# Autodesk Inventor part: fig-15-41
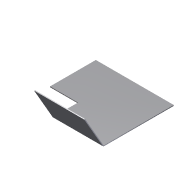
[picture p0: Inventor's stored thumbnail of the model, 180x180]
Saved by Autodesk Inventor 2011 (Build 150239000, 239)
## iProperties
Created: 2005-03
Part Number: fig-15-41
Document SubType Name: Sheet Metal
Designer: CADCIM
Manufacturer: Standard
Standards Organization: Custom
Density: 1 g/cm^3
Sheet Metal Rule: Default
Author: CADCIM
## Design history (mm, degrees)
node "Face1"
  sketch "Sketch1"
    geometry: L1 (31.393, 35.714)-(-19.875, 35.714); L2 (-19.875, 35.714)-(-19.875, 5.625); L3 (-19.875, 5.625)-(-1.5, 5.625); L4 (-1.5, 5.625)-(-1.5, -10.705); L5 (-1.5, -10.705)-(31.393, -10.705); L6 (31.393, -10.705)-(31.393, 35.714)
    constraints: 12 end point, 4 parallel, 1 horizontal, 1 perpendicular
sketch "Sketch3"
  geometry: L1 (18.375, -30.089)-(18.375, 0); L2 (18.375, -46.42)-(18.375, -30.089) reference; L3 (18.375, -30.089)-(0, -30.089) reference; L4 (0, 0)-(51.268, 0) reference
  constraints: 3 point on line, 2 end point, 1 vertical
node "Flange1"
body "Solid1"
face "Plate1" dims "Thickness" = 0.5
sketch "Sketch4"
  geometry: L1 (0, 25)-(-32.893, 25); L2 (-32.893, 25)-(-32.893, 0); 2 other entities
  constraints: 4 end point, 4 other
face "Plate2" dims "d1" = 0.5 (= BendReliefWidth), "d2" = 0.25 (= BendReliefDepth), "d3" = 1 (= MinimumRemnant), "d4" = 0.5 (= BendRadius), "d5" = 25, "d6" = 60 deg, "d7" = 0.5 (= BendRadius), "d8" = 2 (= CornerReliefSize), "d9" = 0.5 (= GapSize), "d10" = 0.5 (= JacobiRadiusSize), "SeamGap" = 0.01, "Thickness" = 0.5
bend "Bend1" dims "d1" = 0.5 (= BendReliefWidth), "d2" = 0.25 (= BendReliefDepth), "d3" = 1 (= MinimumRemnant), "d4" = 0.5 (= BendRadius), "d5" = 25, "d6" = 60 deg, "d7" = 0.5 (= BendRadius), "SeamGap" = 0.01, "Thickness" = 0.5
feature "Corner1" dims "d5" = 25, "d6" = 60 deg, "d8" = 2 (= CornerReliefSize), "d9" = 0.5 (= GapSize), "d10" = 0.5 (= JacobiRadiusSize)
other parameters: "BendRadius" = 0.5 (= Thickness), "BendReliefWidth" = 0.5 (= Thickness), "BendReliefDepth" = 0.25 (= 0.5 x Thickness), "CornerReliefSize" = 2 (= 4 x Thickness), "MinimumRemnant" = 1 (= 2 x Thickness), "TransitionRadius" = 0.5 (= BendRadius), "d0" = 0.5 (= BendRadius), "JacobiRadiusSize" = 0.5 (= Thickness), "GapSize" = 0.5 (= Thickness)
